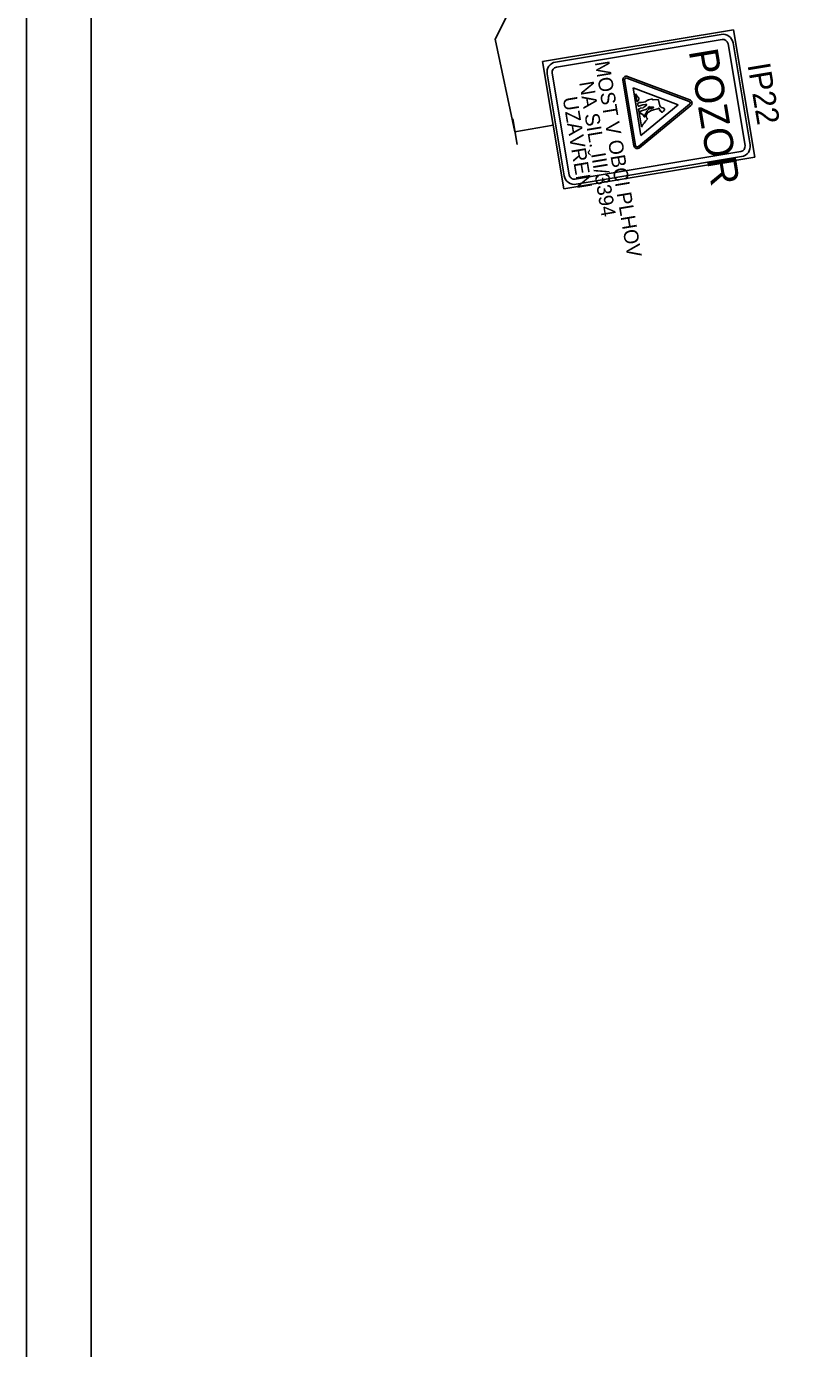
# Model space of a CAD drawing. Extents: x -688893 to -679983, y -1088371 to -1075771.
# Drawn here: x -688893 to -687104, y -1082768 to -1079697 of the extents above; entities that cross this region are included whole.
import ezdxf

# ---------------------------------------------------------------- set-up
doc = ezdxf.new("R2010")
doc.units = 0
for name, color, linetype in [('ramecek', 7, 'Continuous'), ('SDZ', 7, 'Continuous'), ('SDZ ozn', 7, 'Continuous'), ('SDZ plochy', 7, 'Continuous'), ('SDZ symbol', 7, 'Continuous')]:
    doc.layers.add(name, color=color, linetype=linetype)

msp = doc.modelspace()

# ---------------------------------------------------------------- linework, layer by layer
at = {"layer": 'ramecek'}
for points in [[(-679983.4, -1075770.7), (-679983.4, -1088370.7), (-688893.4, -1088370.7), (-688893.4, -1075770.7)], [(-680133.4, -1076070.7), (-680133.4, -1088220.7), (-688743.4, -1088220.7), (-688743.4, -1076070.7)]]:
    msp.add_lwpolyline(points, close=True, dxfattribs=at)
at = {"layer": 'SDZ'}
for p, q in [((-687694.6, -1079778.4), (-687250.8, -1079704.3)), ((-687664, -1079779.4), (-687279.4, -1079715.1)), ((-687250.8, -1079704.3), (-687201.3, -1080000.2)), ((-687662.1, -1079791.2), (-687277.4, -1079727)), ((-687263.6, -1079736.8), (-687224, -1079973.5)), ((-687251.7, -1079734.8), (-687212.2, -1079971.6)), ((-687645.2, -1080074.3), (-687694.6, -1079778.4)), ((-687644.2, -1080043.7), (-687683.8, -1079807)), ((-687632.4, -1080041.7), (-687671.9, -1079805)), ((-687354.1, -1079870.7), (-687498.3, -1079816.7)), ((-687496.9, -1079812.9), (-687352.4, -1079866.9)), ((-687507.7, -1079821.8), (-687482.3, -1079973.8)), ((-687503.7, -1079821.1), (-687478.3, -1079973.2)), ((-687379.4, -1079878.5), (-687484.3, -1079839.2)), ((-687484.3, -1079839.2), (-687465.8, -1079949.8)), ((-687478.2, -1079853.5), (-687474.7, -1079871.8)), ((-687475.7, -1079857.6), (-687478.2, -1079853.5)), ((-687474, -1079860.4), (-687475.7, -1079857.6)), ((-687474.7, -1079871.8), (-687473.3, -1079870.4)), ((-687471, -1079862.4), (-687474, -1079860.4)), ((-687471.9, -1079875.1), (-687473.9, -1079875.6)), ((-687473.9, -1079875.6), (-687472.6, -1079882.2)), ((-687473.3, -1079870.4), (-687471.6, -1079868.6)), ((-687470.9, -1079873.7), (-687471.9, -1079875.1)), ((-687471.7, -1079975.6), (-687352.9, -1079877.6)), ((-687471.6, -1079868.6), (-687470.6, -1079865.6)), ((-687470.4, -1079863.3), (-687471, -1079862.4)), ((-687465.2, -1079873.5), (-687470.9, -1079873.7)), ((-687470.6, -1079865.6), (-687470.2, -1079864.5)), ((-687470.2, -1079864.5), (-687470.4, -1079863.3)), ((-687465.8, -1079949.8), (-687379.4, -1079878.5)), ((-687460.2, -1079872.9), (-687465.2, -1079873.5)), ((-687461.6, -1079879.1), (-687455.6, -1079878.1)), ((-687455.9, -1079871.6), (-687460.2, -1079872.9)), ((-687451.4, -1079868.8), (-687455.9, -1079871.6)), ((-687455.6, -1079878.1), (-687452.5, -1079878)), ((-687452.5, -1079878), (-687454.7, -1079880.8)), ((-687448.6, -1079866.9), (-687451.4, -1079868.8)), ((-687442.4, -1079866), (-687448.6, -1079866.9)), ((-687441.2, -1079865), (-687442.4, -1079866)), ((-687437.3, -1079867.2), (-687441.2, -1079865)), ((-687425.7, -1079866.5), (-687437.3, -1079867.2)), ((-687425.1, -1079867.9), (-687425.7, -1079866.5)), ((-687421.8, -1079881.1), (-687425.1, -1079867.9)), ((-687354, -1079870.8), (-687354, -1079870.8)), ((-687472.6, -1079882.2), (-687470.7, -1079882.3)), ((-687469.7, -1079888.5), (-687471.9, -1079888.8)), ((-687471.9, -1079888.8), (-687470, -1079896.3)), ((-687470.7, -1079882.3), (-687461.6, -1079879.1)), ((-687470, -1079896.3), (-687468.3, -1079896.4)), ((-687465.8, -1079899.3), (-687470, -1079897.7)), ((-687470, -1079897.7), (-687464.8, -1079930.1)), ((-687468.7, -1079888.1), (-687469.7, -1079888.5)), ((-687350.1, -1079880.7), (-687469.2, -1079978.7)), ((-687467.9, -1079886.7), (-687468.7, -1079888.1)), ((-687468.3, -1079896.4), (-687467.2, -1079896)), ((-687460.5, -1079885.5), (-687467.9, -1079886.7)), ((-687467.2, -1079896), (-687466.7, -1079893.9)), ((-687466.7, -1079893.9), (-687462.3, -1079892.3)), ((-687461.4, -1079901.2), (-687465.8, -1079899.3)), ((-687462.3, -1079892.3), (-687457, -1079890.8)), ((-687459.6, -1079903.4), (-687461.4, -1079901.2)), ((-687459.3, -1079884.5), (-687460.5, -1079885.5)), ((-687458.3, -1079906.5), (-687459.6, -1079903.4)), ((-687454.7, -1079880.8), (-687459.3, -1079884.5)), ((-687456.8, -1079906.6), (-687458.3, -1079906.5)), ((-687457, -1079890.8), (-687453, -1079888.7)), ((-687451.8, -1079894.9), (-687456.8, -1079903.1)), ((-687456.8, -1079903.1), (-687456.8, -1079906.6)), ((-687453.6, -1079903.6), (-687449.8, -1079895.6)), ((-687453.1, -1079909.3), (-687453.6, -1079903.6)), ((-687451.4, -1079910.6), (-687453.1, -1079909.3)), ((-687453, -1079888.7), (-687449.1, -1079885)), ((-687449.9, -1079891.1), (-687452, -1079893.3)), ((-687452, -1079893.3), (-687451.8, -1079894.9)), ((-687448.3, -1079889.6), (-687449.9, -1079891.1)), ((-687449.8, -1079895.6), (-687448.6, -1079895.6)), ((-687449.1, -1079885), (-687444.9, -1079882.9)), ((-687448.6, -1079895.6), (-687447.1, -1079894.7)), ((-687444.5, -1079883.2), (-687448.3, -1079889.6)), ((-687447.1, -1079894.7), (-687443.9, -1079893)), ((-687444.9, -1079882.9), (-687444.5, -1079883.2)), ((-687442.9, -1079885.4), (-687444, -1079888.3)), ((-687444, -1079888.3), (-687442.5, -1079888)), ((-687443.9, -1079893), (-687437, -1079890.2)), ((-687441.5, -1079884.1), (-687442.9, -1079885.4)), ((-687442.5, -1079888), (-687439.4, -1079886.7)), ((-687440, -1079884.1), (-687441.5, -1079884.1)), ((-687436.3, -1079884.1), (-687440, -1079884.1)), ((-687439.4, -1079886.7), (-687436.5, -1079885.6)), ((-687437, -1079890.2), (-687430.8, -1079888.9)), ((-687436.5, -1079885.6), (-687435.6, -1079884.8)), ((-687435.6, -1079884.8), (-687436.3, -1079884.1)), ((-687430.8, -1079888.9), (-687427, -1079888.3)), ((-687427, -1079888.3), (-687424.7, -1079887.5)), ((-687424.7, -1079887.5), (-687423.7, -1079886.9)), ((-687423.7, -1079886.9), (-687422.4, -1079887.5)), ((-687422.3, -1079888.3), (-687422.6, -1079890)), ((-687422.6, -1079890), (-687421.9, -1079891.8)), ((-687422.4, -1079887.5), (-687422.3, -1079888.3)), ((-687421.9, -1079891.8), (-687420.5, -1079893)), ((-687420.4, -1079883.7), (-687421.8, -1079881.1)), ((-687420.5, -1079893), (-687418.9, -1079893.7)), ((-687418.2, -1079885.4), (-687420.4, -1079883.7)), ((-687418.9, -1079893.7), (-687418.9, -1079894.8)), ((-687418.9, -1079894.8), (-687418.2, -1079895.7)), ((-687415.1, -1079886.1), (-687418.2, -1079885.4)), ((-687418.2, -1079895.7), (-687416.1, -1079895.5)), ((-687416.1, -1079895.5), (-687413.5, -1079893.2)), ((-687412, -1079887), (-687415.1, -1079886.1)), ((-687413.5, -1079893.2), (-687411.4, -1079890.6)), ((-687410.8, -1079888.5), (-687412, -1079887)), ((-687411.4, -1079890.6), (-687410.8, -1079888.5)), ((-687350.2, -1079880.8), (-687350.2, -1079880.8)), ((-687763.6, -1079911.6), (-687753.7, -1079970.8)), ((-687669.9, -1079926.4), (-687758.7, -1079941.2)), ((-687464.8, -1079930.1), (-687463.3, -1079929.1)), ((-687463.3, -1079929.1), (-687463, -1079927.2)), ((-687463, -1079927.2), (-687461.5, -1079925.3)), ((-687461.5, -1079925.3), (-687460.7, -1079923.5)), ((-687460.7, -1079923.5), (-687458.6, -1079921.7)), ((-687458.6, -1079921.7), (-687457, -1079918.8)), ((-687457, -1079918.8), (-687454.4, -1079916.1)), ((-687454.4, -1079916.1), (-687452.1, -1079913.6)), ((-687452.1, -1079913.6), (-687450.8, -1079911.8)), ((-687450.8, -1079911.8), (-687451.4, -1079910.6)), ((-687201.3, -1080000.2), (-687645.2, -1080074.3)), ((-687233.9, -1079987.4), (-687618.6, -1080051.6)), ((-687231.9, -1079999.2), (-687616.6, -1080063.4))]:
    msp.add_line(p, q, dxfattribs=at)
msp.add_lwpolyline([(-687320.5, -1078761.1), (-687804.8, -1079726.1), (-687758.7, -1079941.2)], dxfattribs=at)
for centre, radius, start, end in [((-687275.4, -1079738.8), 24, 9.4821, 99.4821), ((-687275.4, -1079738.8), 12, 9.4821, 99.4821), ((-687660.1, -1079803), 24, 99.4821, 189.4821), ((-687660.1, -1079803), 12, 99.4821, 189.4821), ((-687499.7, -1079820.5), 8.1, 69.513, 189.4821), ((-687499.7, -1079820.4), 4.05, 69.4478, 189.4821), ((-687355.5, -1079874.5), 4.05, 309.5164, 69.4478), ((-687355.3, -1079874.5), 8.1, 309.4512, 69.513), ((-687474.3, -1079972.4), 8.1, 189.4821, 309.4512), ((-687474.3, -1079972.5), 4.05, 189.4821, 309.5164), ((-687235.9, -1079975.5), 12, 279.4821, 9.4821), ((-687235.9, -1079975.5), 24, 279.4821, 9.4821), ((-687620.5, -1080039.8), 24, 189.4821, 279.4821), ((-687620.5, -1080039.8), 12, 189.4821, 279.4821)]:
    msp.add_arc(centre, radius, start, end, dxfattribs=at)
at = {"layer": 'SDZ plochy'}
for p, q in [((-687250.8, -1079704.3), (-687694.6, -1079778.4)), ((-687279.4, -1079715.1), (-687664, -1079779.4)), ((-687664, -1079779.4), (-687279.4, -1079715.1)), ((-687201.3, -1080000.2), (-687250.8, -1079704.3)), ((-687662.1, -1079791.2), (-687277.4, -1079727)), ((-687277.4, -1079727), (-687662.1, -1079791.2)), ((-687263.6, -1079736.8), (-687224, -1079973.5)), ((-687224, -1079973.5), (-687263.6, -1079736.8)), ((-687212.2, -1079971.6), (-687251.7, -1079734.8)), ((-687251.7, -1079734.8), (-687212.2, -1079971.6)), ((-687694.6, -1079778.4), (-687645.2, -1080074.3)), ((-687683.8, -1079807), (-687644.2, -1080043.7)), ((-687644.2, -1080043.7), (-687683.8, -1079807)), ((-687632.4, -1080041.7), (-687671.9, -1079805)), ((-687671.9, -1079805), (-687632.4, -1080041.7)), ((-687354.1, -1079870.7), (-687498.3, -1079816.7)), ((-687498.3, -1079816.7), (-687354.1, -1079870.7)), ((-687496.9, -1079812.9), (-687352.4, -1079866.9)), ((-687352.4, -1079866.9), (-687496.9, -1079812.9)), ((-687482.3, -1079973.8), (-687507.7, -1079821.8)), ((-687507.7, -1079821.8), (-687482.3, -1079973.8)), ((-687503.7, -1079821.1), (-687478.3, -1079973.2)), ((-687478.3, -1079973.2), (-687503.7, -1079821.1)), ((-687465.8, -1079949.8), (-687484.3, -1079839.2)), ((-687484.3, -1079839.2), (-687379.4, -1079878.5)), ((-687379.4, -1079878.5), (-687484.3, -1079839.2)), ((-687484.3, -1079839.2), (-687465.8, -1079949.8)), ((-687478.2, -1079853.5), (-687474.7, -1079871.8)), ((-687475.7, -1079857.6), (-687478.2, -1079853.5)), ((-687474.7, -1079871.8), (-687478.2, -1079853.5)), ((-687478.2, -1079853.5), (-687475.7, -1079857.6)), ((-687474, -1079860.4), (-687475.7, -1079857.6)), ((-687475.7, -1079857.6), (-687474, -1079860.4)), ((-687474.7, -1079871.8), (-687473.3, -1079870.4)), ((-687473.3, -1079870.4), (-687474.7, -1079871.8)), ((-687471, -1079862.4), (-687474, -1079860.4)), ((-687474, -1079860.4), (-687471, -1079862.4)), ((-687471.9, -1079875.1), (-687473.9, -1079875.6)), ((-687473.9, -1079875.6), (-687471.9, -1079875.1)), ((-687473.9, -1079875.6), (-687472.6, -1079882.2)), ((-687472.6, -1079882.2), (-687473.9, -1079875.6)), ((-687473.3, -1079870.4), (-687471.6, -1079868.6)), ((-687471.6, -1079868.6), (-687473.3, -1079870.4)), ((-687470.9, -1079873.7), (-687471.9, -1079875.1)), ((-687471.9, -1079875.1), (-687470.9, -1079873.7)), ((-687471.7, -1079975.6), (-687352.9, -1079877.6)), ((-687352.9, -1079877.6), (-687471.7, -1079975.6)), ((-687471.6, -1079868.6), (-687470.6, -1079865.6)), ((-687470.6, -1079865.6), (-687471.6, -1079868.6)), ((-687470.4, -1079863.3), (-687471, -1079862.4)), ((-687471, -1079862.4), (-687470.4, -1079863.3)), ((-687465.2, -1079873.5), (-687470.9, -1079873.7)), ((-687470.9, -1079873.7), (-687465.2, -1079873.5)), ((-687470.6, -1079865.6), (-687470.2, -1079864.5)), ((-687470.2, -1079864.5), (-687470.6, -1079865.6)), ((-687470.2, -1079864.5), (-687470.4, -1079863.3)), ((-687470.4, -1079863.3), (-687470.2, -1079864.5)), ((-687379.4, -1079878.5), (-687465.8, -1079949.8)), ((-687465.8, -1079949.8), (-687379.4, -1079878.5)), ((-687460.2, -1079872.9), (-687465.2, -1079873.5)), ((-687465.2, -1079873.5), (-687460.2, -1079872.9)), ((-687461.6, -1079879.1), (-687455.6, -1079878.1)), ((-687455.6, -1079878.1), (-687461.6, -1079879.1)), ((-687455.9, -1079871.6), (-687460.2, -1079872.9)), ((-687460.2, -1079872.9), (-687455.9, -1079871.6)), ((-687451.4, -1079868.8), (-687455.9, -1079871.6)), ((-687455.9, -1079871.6), (-687451.4, -1079868.8)), ((-687455.6, -1079878.1), (-687452.5, -1079878)), ((-687452.5, -1079878), (-687455.6, -1079878.1)), ((-687452.5, -1079878), (-687454.7, -1079880.8)), ((-687454.7, -1079880.8), (-687452.5, -1079878)), ((-687448.6, -1079866.9), (-687451.4, -1079868.8)), ((-687451.4, -1079868.8), (-687448.6, -1079866.9)), ((-687442.4, -1079866), (-687448.6, -1079866.9)), ((-687448.6, -1079866.9), (-687442.4, -1079866)), ((-687441.2, -1079865), (-687442.4, -1079866)), ((-687442.4, -1079866), (-687441.2, -1079865)), ((-687437.3, -1079867.2), (-687441.2, -1079865)), ((-687441.2, -1079865), (-687437.3, -1079867.2)), ((-687425.7, -1079866.5), (-687437.3, -1079867.2)), ((-687437.3, -1079867.2), (-687425.7, -1079866.5)), ((-687425.1, -1079867.9), (-687425.7, -1079866.5)), ((-687425.7, -1079866.5), (-687425.1, -1079867.9)), ((-687421.8, -1079881.1), (-687425.1, -1079867.9)), ((-687425.1, -1079867.9), (-687421.8, -1079881.1)), ((-687472.6, -1079882.2), (-687470.7, -1079882.3)), ((-687470.7, -1079882.3), (-687472.6, -1079882.2)), ((-687469.7, -1079888.5), (-687471.9, -1079888.8)), ((-687471.9, -1079888.8), (-687469.7, -1079888.5)), ((-687471.9, -1079888.8), (-687470, -1079896.3)), ((-687470, -1079896.3), (-687471.9, -1079888.8)), ((-687470.7, -1079882.3), (-687461.6, -1079879.1)), ((-687461.6, -1079879.1), (-687470.7, -1079882.3)), ((-687470, -1079896.3), (-687468.3, -1079896.4)), ((-687468.3, -1079896.4), (-687470, -1079896.3)), ((-687465.8, -1079899.3), (-687470, -1079897.7)), ((-687470, -1079897.7), (-687464.8, -1079930.1)), ((-687464.8, -1079930.1), (-687470, -1079897.7)), ((-687470, -1079897.7), (-687465.8, -1079899.3)), ((-687468.7, -1079888.1), (-687469.7, -1079888.5)), ((-687469.7, -1079888.5), (-687468.7, -1079888.1)), ((-687350.1, -1079880.7), (-687469.2, -1079978.7)), ((-687469.2, -1079978.7), (-687350.1, -1079880.7)), ((-687467.9, -1079886.7), (-687468.7, -1079888.1)), ((-687468.7, -1079888.1), (-687467.9, -1079886.7)), ((-687468.3, -1079896.4), (-687467.2, -1079896)), ((-687467.2, -1079896), (-687468.3, -1079896.4)), ((-687460.5, -1079885.5), (-687467.9, -1079886.7)), ((-687467.9, -1079886.7), (-687460.5, -1079885.5)), ((-687467.2, -1079896), (-687466.7, -1079893.9)), ((-687466.7, -1079893.9), (-687467.2, -1079896)), ((-687466.7, -1079893.9), (-687462.3, -1079892.3)), ((-687462.3, -1079892.3), (-687466.7, -1079893.9)), ((-687461.4, -1079901.2), (-687465.8, -1079899.3)), ((-687465.8, -1079899.3), (-687461.4, -1079901.2)), ((-687462.3, -1079892.3), (-687457, -1079890.8)), ((-687457, -1079890.8), (-687462.3, -1079892.3)), ((-687459.6, -1079903.4), (-687461.4, -1079901.2)), ((-687461.4, -1079901.2), (-687459.6, -1079903.4)), ((-687459.3, -1079884.5), (-687460.5, -1079885.5)), ((-687460.5, -1079885.5), (-687459.3, -1079884.5)), ((-687458.3, -1079906.5), (-687459.6, -1079903.4)), ((-687459.6, -1079903.4), (-687458.3, -1079906.5)), ((-687454.7, -1079880.8), (-687459.3, -1079884.5)), ((-687459.3, -1079884.5), (-687454.7, -1079880.8)), ((-687456.8, -1079906.6), (-687458.3, -1079906.5)), ((-687458.3, -1079906.5), (-687456.8, -1079906.6)), ((-687457, -1079890.8), (-687453, -1079888.7)), ((-687453, -1079888.7), (-687457, -1079890.8)), ((-687451.8, -1079894.9), (-687456.8, -1079903.1)), ((-687456.8, -1079903.1), (-687451.8, -1079894.9)), ((-687456.8, -1079903.1), (-687456.8, -1079906.6)), ((-687456.8, -1079906.6), (-687456.8, -1079903.1)), ((-687453.6, -1079903.6), (-687449.8, -1079895.6)), ((-687449.8, -1079895.6), (-687453.6, -1079903.6)), ((-687453.1, -1079909.3), (-687453.6, -1079903.6)), ((-687453.6, -1079903.6), (-687453.1, -1079909.3)), ((-687451.4, -1079910.6), (-687453.1, -1079909.3)), ((-687453.1, -1079909.3), (-687451.4, -1079910.6)), ((-687453, -1079888.7), (-687449.1, -1079885)), ((-687449.1, -1079885), (-687453, -1079888.7)), ((-687449.9, -1079891.1), (-687452, -1079893.3)), ((-687452, -1079893.3), (-687449.9, -1079891.1)), ((-687452, -1079893.3), (-687451.8, -1079894.9)), ((-687451.8, -1079894.9), (-687452, -1079893.3)), ((-687448.3, -1079889.6), (-687449.9, -1079891.1)), ((-687449.9, -1079891.1), (-687448.3, -1079889.6)), ((-687449.8, -1079895.6), (-687448.6, -1079895.6)), ((-687448.6, -1079895.6), (-687449.8, -1079895.6)), ((-687449.1, -1079885), (-687444.9, -1079882.9)), ((-687444.9, -1079882.9), (-687449.1, -1079885)), ((-687448.6, -1079895.6), (-687447.1, -1079894.7)), ((-687447.1, -1079894.7), (-687448.6, -1079895.6)), ((-687444.5, -1079883.2), (-687448.3, -1079889.6)), ((-687448.3, -1079889.6), (-687444.5, -1079883.2)), ((-687447.1, -1079894.7), (-687443.9, -1079893)), ((-687443.9, -1079893), (-687447.1, -1079894.7)), ((-687444.9, -1079882.9), (-687444.5, -1079883.2)), ((-687444.5, -1079883.2), (-687444.9, -1079882.9)), ((-687444, -1079888.3), (-687442.9, -1079885.4)), ((-687442.9, -1079885.4), (-687444, -1079888.3)), ((-687442.5, -1079888), (-687444, -1079888.3)), ((-687444, -1079888.3), (-687442.5, -1079888)), ((-687443.9, -1079893), (-687437, -1079890.2)), ((-687437, -1079890.2), (-687443.9, -1079893)), ((-687442.9, -1079885.4), (-687441.5, -1079884.1)), ((-687441.5, -1079884.1), (-687442.9, -1079885.4)), ((-687439.4, -1079886.7), (-687442.5, -1079888)), ((-687442.5, -1079888), (-687439.4, -1079886.7)), ((-687441.5, -1079884.1), (-687440, -1079884.1)), ((-687440, -1079884.1), (-687441.5, -1079884.1)), ((-687440, -1079884.1), (-687436.3, -1079884.1)), ((-687436.3, -1079884.1), (-687440, -1079884.1)), ((-687436.5, -1079885.6), (-687439.4, -1079886.7)), ((-687439.4, -1079886.7), (-687436.5, -1079885.6)), ((-687437, -1079890.2), (-687430.8, -1079888.9)), ((-687430.8, -1079888.9), (-687437, -1079890.2)), ((-687435.6, -1079884.8), (-687436.5, -1079885.6)), ((-687436.5, -1079885.6), (-687435.6, -1079884.8)), ((-687436.3, -1079884.1), (-687435.6, -1079884.8)), ((-687435.6, -1079884.8), (-687436.3, -1079884.1)), ((-687430.8, -1079888.9), (-687427, -1079888.3)), ((-687427, -1079888.3), (-687430.8, -1079888.9)), ((-687427, -1079888.3), (-687424.7, -1079887.5)), ((-687424.7, -1079887.5), (-687427, -1079888.3)), ((-687424.7, -1079887.5), (-687423.7, -1079886.9)), ((-687423.7, -1079886.9), (-687424.7, -1079887.5)), ((-687423.7, -1079886.9), (-687422.4, -1079887.5)), ((-687422.4, -1079887.5), (-687423.7, -1079886.9)), ((-687422.3, -1079888.3), (-687422.6, -1079890)), ((-687422.6, -1079890), (-687422.3, -1079888.3)), ((-687422.6, -1079890), (-687421.9, -1079891.8)), ((-687421.9, -1079891.8), (-687422.6, -1079890)), ((-687422.4, -1079887.5), (-687422.3, -1079888.3)), ((-687422.3, -1079888.3), (-687422.4, -1079887.5)), ((-687421.9, -1079891.8), (-687420.5, -1079893)), ((-687420.5, -1079893), (-687421.9, -1079891.8)), ((-687420.4, -1079883.7), (-687421.8, -1079881.1)), ((-687421.8, -1079881.1), (-687420.4, -1079883.7)), ((-687420.5, -1079893), (-687418.9, -1079893.7)), ((-687418.9, -1079893.7), (-687420.5, -1079893)), ((-687418.2, -1079885.4), (-687420.4, -1079883.7)), ((-687420.4, -1079883.7), (-687418.2, -1079885.4)), ((-687418.9, -1079893.7), (-687418.9, -1079894.8)), ((-687418.9, -1079894.8), (-687418.9, -1079893.7)), ((-687418.9, -1079894.8), (-687418.2, -1079895.7)), ((-687418.2, -1079895.7), (-687418.9, -1079894.8)), ((-687415.1, -1079886.1), (-687418.2, -1079885.4)), ((-687418.2, -1079885.4), (-687415.1, -1079886.1)), ((-687418.2, -1079895.7), (-687416.1, -1079895.5)), ((-687416.1, -1079895.5), (-687418.2, -1079895.7)), ((-687416.1, -1079895.5), (-687413.5, -1079893.2)), ((-687413.5, -1079893.2), (-687416.1, -1079895.5)), ((-687412, -1079887), (-687415.1, -1079886.1)), ((-687415.1, -1079886.1), (-687412, -1079887)), ((-687413.5, -1079893.2), (-687411.4, -1079890.6)), ((-687411.4, -1079890.6), (-687413.5, -1079893.2)), ((-687410.8, -1079888.5), (-687412, -1079887)), ((-687412, -1079887), (-687410.8, -1079888.5)), ((-687411.4, -1079890.6), (-687410.8, -1079888.5)), ((-687410.8, -1079888.5), (-687411.4, -1079890.6)), ((-687464.8, -1079930.1), (-687463.3, -1079929.1)), ((-687463.3, -1079929.1), (-687464.8, -1079930.1)), ((-687463.3, -1079929.1), (-687463, -1079927.2)), ((-687463, -1079927.2), (-687463.3, -1079929.1)), ((-687463, -1079927.2), (-687461.5, -1079925.3)), ((-687461.5, -1079925.3), (-687463, -1079927.2)), ((-687461.5, -1079925.3), (-687460.7, -1079923.5)), ((-687460.7, -1079923.5), (-687461.5, -1079925.3)), ((-687460.7, -1079923.5), (-687458.6, -1079921.7)), ((-687458.6, -1079921.7), (-687460.7, -1079923.5)), ((-687458.6, -1079921.7), (-687457, -1079918.8)), ((-687457, -1079918.8), (-687458.6, -1079921.7)), ((-687457, -1079918.8), (-687454.4, -1079916.1)), ((-687454.4, -1079916.1), (-687457, -1079918.8)), ((-687454.4, -1079916.1), (-687452.1, -1079913.6)), ((-687452.1, -1079913.6), (-687454.4, -1079916.1)), ((-687452.1, -1079913.6), (-687450.8, -1079911.8)), ((-687450.8, -1079911.8), (-687452.1, -1079913.6)), ((-687450.8, -1079911.8), (-687451.4, -1079910.6)), ((-687451.4, -1079910.6), (-687450.8, -1079911.8)), ((-687645.2, -1080074.3), (-687201.3, -1080000.2)), ((-687233.9, -1079987.4), (-687618.6, -1080051.6)), ((-687618.6, -1080051.6), (-687233.9, -1079987.4)), ((-687616.6, -1080063.4), (-687231.9, -1079999.2)), ((-687231.9, -1079999.2), (-687616.6, -1080063.4))]:
    msp.add_line(p, q, dxfattribs=at)
for centre, radius, start, end in [((-687275.4, -1079738.8), 24, 9.4821, 99.4821), ((-687275.4, -1079738.8), 24, 9.4821, 99.4821), ((-687275.4, -1079738.8), 12, 9.4821, 99.4821), ((-687275.4, -1079738.8), 12, 9.4821, 99.4821), ((-687660.1, -1079803), 24, 99.4821, 189.4821), ((-687660.1, -1079803), 24, 99.4821, 189.4821), ((-687660.1, -1079803), 12, 99.4821, 189.4821), ((-687660.1, -1079803), 12, 99.4821, 189.4821), ((-687499.7, -1079820.5), 8.1, 69.513, 189.4821), ((-687499.7, -1079820.5), 8.1, 69.513, 189.4821), ((-687499.7, -1079820.4), 4.05, 69.4478, 189.4821), ((-687499.7, -1079820.4), 4.05, 69.4478, 189.4821), ((-687355.5, -1079874.5), 4.05, 309.5164, 69.4478), ((-687355.5, -1079874.5), 4.05, 309.5164, 69.4478), ((-687355.3, -1079874.5), 8.1, 309.4512, 69.513), ((-687355.3, -1079874.5), 8.1, 309.4512, 69.513), ((-687474.3, -1079972.4), 8.1, 189.4821, 309.4512), ((-687474.3, -1079972.4), 8.1, 189.4821, 309.4512), ((-687474.3, -1079972.5), 4.05, 189.4821, 309.5164), ((-687474.3, -1079972.5), 4.05, 189.4821, 309.5164), ((-687235.9, -1079975.5), 12, 279.4821, 9.4821), ((-687235.9, -1079975.5), 12, 279.4821, 9.4821), ((-687235.9, -1079975.5), 24, 279.4821, 9.4821), ((-687235.9, -1079975.5), 24, 279.4821, 9.4821), ((-687620.5, -1080039.8), 24, 189.4821, 279.4821), ((-687620.5, -1080039.8), 24, 189.4821, 279.4821), ((-687620.5, -1080039.8), 12, 189.4821, 279.4821), ((-687620.5, -1080039.8), 12, 189.4821, 279.4821)]:
    msp.add_arc(centre, radius, start, end, dxfattribs=at)

# ---------------------------------------------------------------- texts
at = {"layer": 'SDZ ozn'}
msp.add_text('IP22', height=52.5, rotation=279.4821, dxfattribs=at).set_placement((-687218.4, -1079785.6))
at = {"layer": 'SDZ symbol'}
for s, height, p in [('POZOR', 67.5, (-687355, -1079753.9)), ('MOST V OBCI PLHOV', 33.75, (-687573.1, -1079779.9)), ('NA SIL. III/3394', 33.75, (-687609.5, -1079826.8)), ('UZAVŘEN', 33.75, (-687647.8, -1079862.7))]:
    msp.add_text(s, height=height, rotation=279.4821, dxfattribs=at).set_placement(p)

doc.saveas('drawing.dxf')
